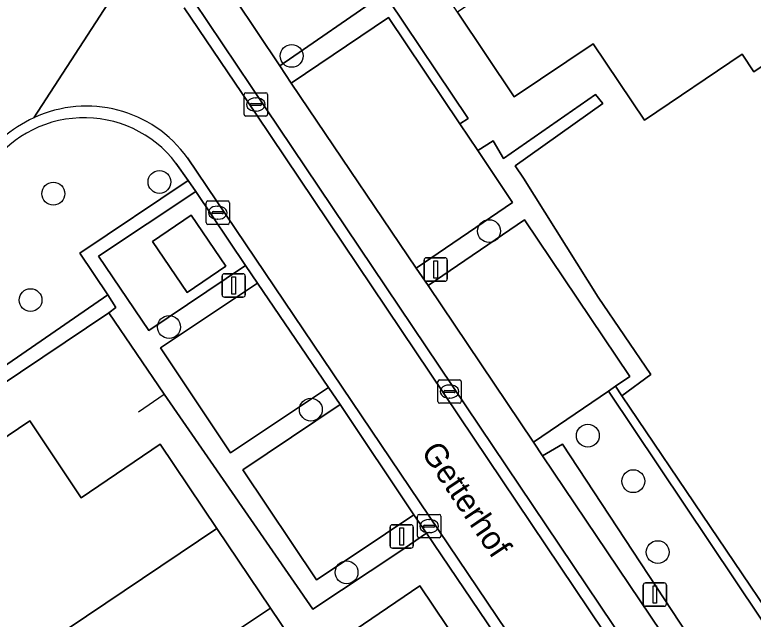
# Model space of a CAD drawing. Extents: x 158793 to 159888, y 384317 to 385256.
# Drawn here: x 158913.64 to 158945.21, y 384644.03 to 384669.88 of the extents above; entities that cross this region are included whole.
import ezdxf

# ---------------------------------------------------------------- set-up
doc = ezdxf.new("R2010")
doc.units = 0
for name, color, linetype in [('IMGEO_Berm_groen', 7, 'Continuous'), ('IMGEO_Boom', 7, 'Continuous'), ('IMGEO_Erf', 7, 'Continuous'), ('IMGEO_Groenvoorziening', 7, 'Continuous'), ('IMGEO_Haag', 7, 'Continuous'), ('IMGEO_Hek', 7, 'Continuous'), ('IMGEO_Kolk', 7, 'Continuous'), ('IMGEO_Lichtmast', 7, 'Continuous'), ('IMGEO_Openbare_ruimte_label', 7, 'Continuous'), ('IMGEO_Pand', 7, 'Continuous'), ('IMGEO_Parkeervlak_open', 7, 'Continuous'), ('IMGEO_Rijbaan_lokaal_open', 7, 'Continuous'), ('IMGEO_Voetpad_open', 7, 'Continuous')]:
    doc.layers.add(name, color=color, linetype=linetype)

msp = doc.modelspace()

# ---------------------------------------------------------------- linework, layer by layer
at = {"layer": 'IMGEO_Berm_groen'}
for points in [[(158917.62, 384657.908), (158916.41, 384659.683), (158921.052, 384662.795), (158920.527, 384663.541)], [(158914.37, 384620.747), (158915.141, 384621.25), (158911.908, 384626.271), (158911.057, 384625.702), (158910.473, 384626.512), (158909.391, 384625.832), (158899.194, 384641.02), (158904.609, 384644.899), (158902.885, 384647.758), (158917.62, 384657.908)]]:
    msp.add_lwpolyline(points, dxfattribs=at)
msp.add_arc((158916.599, 384660.523), 4.953, 37.5405, 147.1324, dxfattribs=at)
at = {"layer": 'IMGEO_Boom'}
for centre in [(158925.473, 384668.121), (158919.821, 384662.733), (158915.283, 384662.229), (158933.915, 384660.629), (158914.31, 384657.679), (158920.233, 384656.527), (158926.294, 384652.998), (158938.137, 384651.883), (158940.079, 384649.936), (158941.126, 384646.903), (158927.821, 384646.037)]:
    msp.add_circle(centre, 0.489, dxfattribs=at)
at = {"layer": 'IMGEO_Erf'}
for points in [[(158970.042, 384650.292), (158941.462, 384692.581), (158927.478, 384683.208), (158931.293, 384677.308), (158928.892, 384675.59), (158929.234, 384675.051), (158928.67, 384674.688), (158930.599, 384671.589), (158929.431, 384670.782), (158929.615, 384670.527), (158933.026, 384665.451), (158932.663, 384665.215), (158933.428, 384664.074), (158934.085, 384664.494), (158934.527, 384663.737), (158938.467, 384666.472), (158938.773, 384666.087), (158935.034, 384663.418), (158935.39, 384662.897), (158938.577, 384657.798), (158940.832, 384654.504), (158939.596, 384653.583), (158950.919, 384636.829)], [(158904.737, 384643.112), (158907.129, 384644.742), (158905.762, 384646.758), (158914.28, 384652.511), (158916.47, 384649.231), (158919.852, 384651.521), (158922.28, 384647.917), (158924.575, 384644.51), (158926.138, 384642.19), (158930.948, 384645.466), (158934.462, 384640.251)]]:
    msp.add_lwpolyline(points, dxfattribs=at)
for points in [[(158947.724, 384673.172), (158949.095, 384671.141), (158948.169, 384670.516), (158948.678, 384669.761), (158945.239, 384667.438), (158944.73, 384668.193), (158940.56, 384665.377), (158938.371, 384668.635), (158934.992, 384666.367), (158932.559, 384669.992), (158930.189, 384673.523), (158933.543, 384675.788), (158931.351, 384679.049), (158936.953, 384682.824), (158934.795, 384686.024), (158938.817, 384688.731), (158942.46, 384683.305), (158940.633, 384682.078), (158943.587, 384677.678), (158946.74, 384679.793), (158950.125, 384674.776)], [(158935.269, 384640.755), (158935.742, 384641.055), (158931.239, 384647.707), (158930.053, 384646.895), (158926.376, 384644.46), (158920.02, 384653.654), (158917.65, 384657.141), (158903.486, 384647.632), (158905.26, 384644.832), (158899.805, 384640.906), (158909.685, 384626.219), (158910.802, 384626.858), (158911.256, 384626.177), (158922.042, 384633.454), (158922.226, 384633.163), (158925.099, 384628.623), (158936.517, 384636.347), (158935.783, 384637.416), (158937.012, 384638.256)]]:
    msp.add_lwpolyline(points, close=True, dxfattribs=at)
at = {"layer": 'IMGEO_Groenvoorziening'}
msp.add_lwpolyline([(158922.109, 384671.989), (158924.962, 384667.694), (158929.431, 384670.782), (158930.599, 384671.589), (158928.67, 384674.688), (158928.077, 384675.641), (158930.702, 384677.442), (158927, 384683.401), (158941.507, 384693.215), (158970.058, 384651.22), (158977.555, 384656.193), (158975.853, 384658.793), (158971.165, 384655.643), (158941.388, 384699.818)], dxfattribs=at)
for points in [[(158929.608, 384669.767), (158932.663, 384665.215), (158933.026, 384665.451), (158929.615, 384670.527), (158929.431, 384670.782), (158924.962, 384667.694), (158925.456, 384666.95)], [(158938.577, 384657.798), (158935.39, 384662.897), (158935.034, 384663.418), (158938.773, 384666.087), (158938.467, 384666.472), (158934.527, 384663.737), (158934.085, 384664.494), (158933.428, 384664.074), (158934.92, 384661.851), (158930.791, 384659.038), (158931.31, 384658.301), (158935.423, 384661.113), (158939.935, 384654.417), (158939.313, 384653.993), (158939.596, 384653.583), (158940.832, 384654.504)], [(158919.866, 384655.634), (158924.01, 384658.409), (158923.499, 384659.163), (158919.366, 384656.377), (158917.218, 384659.56), (158921.38, 384662.329), (158921.052, 384662.795), (158916.41, 384659.683), (158917.62, 384657.908), (158917.963, 384657.364), (158917.65, 384657.141), (158920.02, 384653.654), (158926.376, 384644.46), (158930.053, 384646.895), (158931.239, 384647.707), (158930.702, 384648.501), (158928.269, 384646.876), (158926.536, 384645.718), (158923.383, 384650.415), (158927.544, 384653.21), (158927.045, 384653.945), (158922.866, 384651.155)], [(158917.65, 384657.141), (158917.963, 384657.364), (158917.62, 384657.908), (158902.885, 384647.758), (158904.609, 384644.899), (158899.194, 384641.02), (158909.391, 384625.832), (158910.473, 384626.512), (158911.057, 384625.702), (158911.908, 384626.271), (158922.226, 384633.163), (158922.042, 384633.454), (158911.256, 384626.177), (158910.802, 384626.858), (158909.685, 384626.219), (158899.805, 384640.906), (158905.26, 384644.832), (158903.486, 384647.632)], [(158939.596, 384653.583), (158939.313, 384653.993), (158939.017, 384653.792), (158950.928, 384636.006), (158951.302, 384636.262), (158950.919, 384636.829)], [(158939.017, 384653.792), (158935.807, 384651.605), (158936.203, 384651.016), (158937.049, 384651.521), (158951.101, 384630.138), (158952.761, 384631.247), (158949.979, 384635.355), (158950.928, 384636.006)], [(158936.203, 384651.016), (158950.52, 384629.75), (158951.101, 384630.138), (158937.049, 384651.521)]]:
    msp.add_lwpolyline(points, close=True, dxfattribs=at)
at = {"layer": 'IMGEO_Haag'}
for points in [[(158929.615, 384670.527), (158929.431, 384670.782), (158924.962, 384667.694), (158925.456, 384666.95), (158929.608, 384669.767), (158932.663, 384665.215), (158933.026, 384665.451)], [(158938.577, 384657.798), (158935.39, 384662.897), (158935.034, 384663.418), (158938.773, 384666.087), (158938.467, 384666.472), (158934.527, 384663.737), (158934.085, 384664.494), (158933.428, 384664.074), (158934.92, 384661.851), (158930.791, 384659.038), (158931.31, 384658.301), (158935.423, 384661.113), (158939.935, 384654.417), (158939.313, 384653.993), (158939.596, 384653.583), (158940.832, 384654.504)], [(158939.596, 384653.583), (158939.313, 384653.993), (158939.017, 384653.792), (158950.928, 384636.006), (158951.302, 384636.262), (158950.919, 384636.829)], [(158936.203, 384651.016), (158950.52, 384629.75), (158951.101, 384630.138), (158937.049, 384651.521)]]:
    msp.add_lwpolyline(points, close=True, dxfattribs=at)
at = {"layer": 'IMGEO_Hek'}
msp.add_lwpolyline([(158918.924, 384652.902), (158920.02, 384653.654), (158917.65, 384657.141), (158903.486, 384647.632), (158905.26, 384644.832)], dxfattribs=at)
at = {"layer": 'IMGEO_Kolk'}
for p, q in [((158923.441, 384665.618), (158923.441, 384666.47)), ((158923.516, 384666.544), (158924.368, 384666.544)), ((158923.929, 384666.324), (158923.954, 384666.324)), ((158924.442, 384666.47), (158924.442, 384665.618)), ((158923.7, 384666.038), (158923.7, 384666.05)), ((158924.138, 384666.001), (158923.74, 384666.001)), ((158923.743, 384666.087), (158924.141, 384666.087)), ((158924.184, 384666.05), (158924.184, 384666.038)), ((158923.952, 384665.764), (158923.927, 384665.764)), ((158924.368, 384665.544), (158923.516, 384665.544)), ((158921.813, 384660.992), (158921.813, 384661.844)), ((158921.888, 384661.918), (158922.74, 384661.918)), ((158922.814, 384661.844), (158922.814, 384660.992)), ((158922.301, 384661.698), (158922.326, 384661.698)), ((158922.072, 384661.412), (158922.072, 384661.424)), ((158922.51, 384661.375), (158922.112, 384661.375)), ((158922.115, 384661.461), (158922.513, 384661.461)), ((158922.556, 384661.424), (158922.556, 384661.412)), ((158922.74, 384660.918), (158921.888, 384660.918)), ((158922.324, 384661.138), (158922.299, 384661.138)), ((158931.798, 384654.269), (158932.65, 384654.269)), ((158931.723, 384653.343), (158931.723, 384654.195)), ((158932.211, 384654.049), (158932.236, 384654.049)), ((158932.724, 384654.195), (158932.724, 384653.343)), ((158931.982, 384653.763), (158931.982, 384653.775)), ((158932.42, 384653.726), (158932.022, 384653.726)), ((158932.025, 384653.812), (158932.423, 384653.812)), ((158932.466, 384653.775), (158932.466, 384653.763)), ((158932.234, 384653.489), (158932.209, 384653.489)), ((158932.65, 384653.269), (158931.798, 384653.269)), ((158930.852, 384647.589), (158930.852, 384648.441)), ((158930.927, 384648.515), (158931.779, 384648.515)), ((158931.34, 384648.295), (158931.365, 384648.295)), ((158931.853, 384648.441), (158931.853, 384647.589)), ((158931.111, 384648.009), (158931.111, 384648.021)), ((158931.549, 384647.972), (158931.151, 384647.972)), ((158931.154, 384648.058), (158931.552, 384648.058)), ((158931.595, 384648.021), (158931.595, 384648.009)), ((158931.363, 384647.735), (158931.338, 384647.735)), ((158931.779, 384647.515), (158930.927, 384647.515))]:
    msp.add_line(p, q, dxfattribs=at)
for points in [[(158923.441, 384665.618), (158923.441, 384666.47)], [(158923.516, 384666.544), (158924.368, 384666.544)], [(158924.442, 384666.47), (158924.442, 384665.618)], [(158924.368, 384665.544), (158923.516, 384665.544)], [(158921.813, 384660.992), (158921.813, 384661.844)], [(158921.888, 384661.918), (158922.74, 384661.918)], [(158922.814, 384661.844), (158922.814, 384660.992)], [(158922.74, 384660.918), (158921.888, 384660.918)], [(158931.798, 384654.269), (158932.65, 384654.269)], [(158931.723, 384653.343), (158931.723, 384654.195)], [(158932.724, 384654.195), (158932.724, 384653.343)], [(158932.65, 384653.269), (158931.798, 384653.269)], [(158930.852, 384647.589), (158930.852, 384648.441)], [(158930.927, 384648.515), (158931.779, 384648.515)], [(158931.853, 384648.441), (158931.853, 384647.589)], [(158931.779, 384647.515), (158930.927, 384647.515)]]:
    msp.add_lwpolyline(points, dxfattribs=at)
for centre, radius, start, end in [((158923.518, 384666.468), 0.0765, 91.552, 178.448), ((158923.518, 384666.468), 0.0765, 91.552, 178.448), ((158924.366, 384666.468), 0.0765, 1.552, 88.448), ((158924.366, 384666.468), 0.0765, 1.552, 88.448), ((158923.74, 384666.047), 0.0403, 85.8775, 175.7526), ((158923.737, 384666.037), 0.0366, 178.938, 274.7102), ((158924.141, 384666.044), 0.043, 264.8664, 352.4533), ((158924.145, 384666.049), 0.0386, 1.7309, 96.639), ((158923.518, 384665.62), 0.0765, 181.552, 268.448), ((158923.518, 384665.62), 0.0765, 181.552, 268.448), ((158924.366, 384665.62), 0.0765, 271.552, 358.448), ((158924.366, 384665.62), 0.0765, 271.552, 358.448), ((158921.89, 384661.842), 0.0765, 91.552, 178.448), ((158921.89, 384661.842), 0.0765, 91.552, 178.448), ((158922.738, 384661.842), 0.0765, 1.552, 88.448), ((158922.738, 384661.842), 0.0765, 1.552, 88.448), ((158922.112, 384661.421), 0.0403, 85.8775, 175.7526), ((158922.109, 384661.411), 0.0366, 178.938, 274.7102), ((158922.513, 384661.418), 0.043, 264.8664, 352.4533), ((158922.517, 384661.423), 0.0386, 1.7309, 96.639), ((158921.89, 384660.994), 0.0765, 181.552, 268.448), ((158921.89, 384660.994), 0.0765, 181.552, 268.448), ((158922.738, 384660.994), 0.0765, 271.552, 358.448), ((158922.738, 384660.994), 0.0765, 271.552, 358.448), ((158931.8, 384654.193), 0.0765, 91.552, 178.448), ((158931.8, 384654.193), 0.0765, 91.552, 178.448), ((158932.648, 384654.193), 0.0765, 1.552, 88.448), ((158932.648, 384654.193), 0.0765, 1.552, 88.448), ((158932.022, 384653.772), 0.0403, 85.8775, 175.7526), ((158932.019, 384653.762), 0.0366, 178.938, 274.7102), ((158932.423, 384653.769), 0.043, 264.8664, 352.4533), ((158932.427, 384653.774), 0.0386, 1.7309, 96.639), ((158931.8, 384653.345), 0.0765, 181.552, 268.448), ((158931.8, 384653.345), 0.0765, 181.552, 268.448), ((158932.648, 384653.345), 0.0765, 271.552, 358.448), ((158932.648, 384653.345), 0.0765, 271.552, 358.448), ((158930.929, 384648.439), 0.0765, 91.552, 178.448), ((158930.929, 384648.439), 0.0765, 91.552, 178.448), ((158931.777, 384648.439), 0.0765, 1.552, 88.448), ((158931.777, 384648.439), 0.0765, 1.552, 88.448), ((158931.151, 384648.018), 0.0403, 85.8775, 175.7526), ((158931.148, 384648.008), 0.0366, 178.938, 274.7102), ((158931.552, 384648.015), 0.043, 264.8664, 352.4533), ((158931.556, 384648.02), 0.0386, 1.7309, 96.639), ((158930.929, 384647.591), 0.0765, 181.552, 268.448), ((158930.929, 384647.591), 0.0765, 181.552, 268.448), ((158931.777, 384647.591), 0.0765, 271.552, 358.448), ((158931.777, 384647.591), 0.0765, 271.552, 358.448)]:
    msp.add_arc(centre, radius, start, end, dxfattribs=at)
for centre, major_axis, ratio, start_param, end_param in [((158923.928, 384666.044), (-0.387, 0.002), 0.722429, 4.712389, 7.853982), ((158923.953, 384666.044), (-0.39, 0.002), 0.717154, 1.570796, 4.712389), ((158922.3, 384661.418), (-0.387, 0.002), 0.722429, 4.712389, 7.853982), ((158922.325, 384661.418), (-0.39, 0.002), 0.717154, 1.570796, 4.712389), ((158932.21, 384653.769), (-0.387, 0.002), 0.722429, 4.712389, 7.853982), ((158932.235, 384653.769), (-0.39, 0.002), 0.717154, 1.570796, 4.712389), ((158931.339, 384648.015), (-0.387, 0.002), 0.722429, 4.712389, 7.853982), ((158931.364, 384648.015), (-0.39, 0.002), 0.717154, 1.570796, 4.712389)]:
    msp.add_ellipse(centre, major_axis=major_axis, ratio=ratio, start_param=start_param, end_param=end_param, dxfattribs=at)
at = {"layer": 'IMGEO_Lichtmast'}
for p, q in [((158931.135, 384658.588), (158931.135, 384659.388)), ((158931.135, 384659.388), (158931.135, 384658.588)), ((158931.235, 384659.488), (158932.025, 384659.488)), ((158932.025, 384659.488), (158931.235, 384659.488)), ((158932.125, 384659.388), (158932.125, 384658.588)), ((158932.125, 384658.588), (158932.125, 384659.388)), ((158922.501, 384657.906), (158922.501, 384658.706)), ((158922.501, 384658.706), (158922.501, 384657.906)), ((158922.601, 384658.806), (158923.391, 384658.806)), ((158923.391, 384658.806), (158922.601, 384658.806)), ((158923.491, 384658.706), (158923.491, 384657.906)), ((158923.491, 384657.906), (158923.491, 384658.706)), ((158932.025, 384658.488), (158931.235, 384658.488)), ((158931.235, 384658.488), (158932.025, 384658.488)), ((158923.391, 384657.806), (158922.601, 384657.806)), ((158922.601, 384657.806), (158923.391, 384657.806)), ((158929.682, 384647.173), (158929.682, 384647.973)), ((158929.682, 384647.973), (158929.682, 384647.173)), ((158929.782, 384648.073), (158930.572, 384648.073)), ((158930.572, 384648.073), (158929.782, 384648.073)), ((158930.672, 384647.973), (158930.672, 384647.173)), ((158930.672, 384647.173), (158930.672, 384647.973)), ((158930.572, 384647.073), (158929.782, 384647.073)), ((158929.782, 384647.073), (158930.572, 384647.073)), ((158940.509, 384644.689), (158940.509, 384645.489)), ((158940.509, 384645.489), (158940.509, 384644.689)), ((158940.609, 384645.589), (158941.399, 384645.589)), ((158941.399, 384645.589), (158940.609, 384645.589)), ((158941.499, 384645.489), (158941.499, 384644.689)), ((158941.499, 384644.689), (158941.499, 384645.489)), ((158941.399, 384644.589), (158940.609, 384644.589)), ((158940.609, 384644.589), (158941.399, 384644.589))]:
    msp.add_line(p, q, dxfattribs=at)
for points in [[(158931.555, 384659.363), (158931.705, 384659.363), (158931.705, 384658.613), (158931.555, 384658.613), (158931.555, 384659.363)], [(158922.921, 384658.681), (158923.071, 384658.681), (158923.071, 384657.931), (158922.921, 384657.931), (158922.921, 384658.681)], [(158930.102, 384647.948), (158930.252, 384647.948), (158930.252, 384647.198), (158930.102, 384647.198), (158930.102, 384647.948)], [(158940.929, 384645.464), (158941.079, 384645.464), (158941.079, 384644.714), (158940.929, 384644.714), (158940.929, 384645.464)]]:
    msp.add_lwpolyline(points, dxfattribs=at)
for centre, start, end in [((158931.235, 384659.388), 90, 180), ((158931.235, 384659.388), 90, 180), ((158932.025, 384659.388), 0, 90), ((158932.025, 384659.388), 360, 90), ((158922.601, 384658.706), 90, 180), ((158922.601, 384658.706), 90, 180), ((158923.391, 384658.706), 0, 90), ((158923.391, 384658.706), 360, 90), ((158931.235, 384658.588), 180, 270), ((158931.235, 384658.588), 180, 270), ((158932.025, 384658.588), 270, 0), ((158932.025, 384658.588), 270, 0), ((158922.601, 384657.906), 180, 270), ((158922.601, 384657.906), 180, 270), ((158923.391, 384657.906), 270, 0), ((158923.391, 384657.906), 270, 0), ((158929.782, 384647.973), 90, 180), ((158929.782, 384647.973), 90, 180), ((158930.572, 384647.973), 0, 90), ((158930.572, 384647.973), 360, 90), ((158929.782, 384647.173), 180, 270), ((158929.782, 384647.173), 180, 270), ((158930.572, 384647.173), 270, 0), ((158930.572, 384647.173), 270, 0), ((158940.609, 384645.489), 90, 180), ((158940.609, 384645.489), 90, 180), ((158941.399, 384645.489), 0, 90), ((158941.399, 384645.489), 360, 90), ((158940.609, 384644.689), 180, 270), ((158940.609, 384644.689), 180, 270), ((158941.399, 384644.689), 270, 0), ((158941.399, 384644.689), 270, 0)]:
    msp.add_arc(centre, 0.1, start, end, dxfattribs=at)
at = {"layer": 'IMGEO_Pand'}
for points in [[(158947.724, 384673.172), (158950.125, 384674.776), (158946.74, 384679.793), (158943.587, 384677.678), (158943.725, 384677.475), (158932.559, 384669.992), (158934.992, 384666.367), (158938.371, 384668.635), (158940.56, 384665.377), (158944.73, 384668.193), (158945.239, 384667.438), (158948.678, 384669.761), (158948.169, 384670.516), (158949.095, 384671.141)], [(158921.004, 384658.011), (158922.656, 384659.135), (158921.175, 384661.311), (158919.523, 384660.186)], [(158922.28, 384647.917), (158919.852, 384651.521), (158916.47, 384649.231), (158914.28, 384652.511), (158905.762, 384646.758), (158907.129, 384644.742), (158904.737, 384643.112), (158907.976, 384638.304)], [(158918.797, 384640.665), (158924.575, 384644.51), (158922.28, 384647.917), (158907.976, 384638.304), (158911.211, 384633.503), (158913.616, 384635.123), (158915.091, 384632.933), (158915.823, 384633.472), (158916.324, 384632.791), (158919.879, 384635.339), (158919.342, 384636.067), (158920.865, 384637.19), (158921.037, 384637.317)], [(158930.948, 384645.466), (158926.138, 384642.19), (158924.575, 384644.51), (158918.797, 384640.665), (158921.037, 384637.317), (158920.865, 384637.19), (158922.204, 384635.199), (158925.241, 384637.242), (158925.827, 384636.371), (158926.167, 384636.6), (158927.06, 384635.272), (158934.462, 384640.251)]]:
    msp.add_lwpolyline(points, close=True, dxfattribs=at)
at = {"layer": 'IMGEO_Parkeervlak_open'}
for points in [[(158932.663, 384665.215), (158929.608, 384669.767), (158925.456, 384666.95), (158926.191, 384665.854), (158930.791, 384659.038), (158934.92, 384661.851), (158933.428, 384664.074)], [(158935.423, 384661.113), (158931.31, 384658.301), (158935.807, 384651.605), (158939.017, 384653.792), (158939.313, 384653.993), (158939.935, 384654.417)], [(158924.01, 384658.409), (158919.866, 384655.634), (158922.866, 384651.155), (158927.045, 384653.945)], [(158927.544, 384653.21), (158923.383, 384650.415), (158926.536, 384645.718), (158928.269, 384646.876), (158930.702, 384648.501)]]:
    msp.add_lwpolyline(points, close=True, dxfattribs=at)
at = {"layer": 'IMGEO_Rijbaan_lokaal_open'}
for points in [[(158919.564, 384673.366), (158914.448, 384665.471)], [(158914.448, 384665.471), (158919.564, 384673.366)], [(158920.881, 384670.173), (158923.955, 384665.633), (158949.957, 384626.932), (158968.418, 384639.524), (158968.134, 384639.947), (158950.085, 384627.638), (158924.353, 384665.905), (158921.285, 384670.455)], [(158941.972, 384632.67), (158949.064, 384622.099), (158970.35, 384636.65), (158968.418, 384639.524), (158949.957, 384626.932), (158923.955, 384665.633), (158920.881, 384670.173)], [(158920.527, 384663.541), (158921.052, 384662.795), (158921.38, 384662.329), (158923.499, 384659.163), (158924.01, 384658.409), (158927.045, 384653.945), (158927.544, 384653.21), (158930.702, 384648.501), (158931.239, 384647.707), (158935.742, 384641.055), (158937.439, 384638.548), (158937.764, 384638.068), (158939.325, 384635.681), (158916.548, 384620.432), (158916.491, 384620.393), (158916.788, 384619.978), (158916.847, 384620.015), (158940.033, 384635.577), (158921.019, 384663.762)], [(158921.019, 384663.762), (158940.033, 384635.577), (158916.847, 384620.015), (158916.788, 384619.978), (158918.623, 384617.027), (158918.871, 384617.212), (158941.972, 384632.67)]]:
    msp.add_lwpolyline(points, dxfattribs=at)
for centre, radius, start, end in [((158916.701, 384660.648), 5.324, 35.8028, 115.0399), ((158916.701, 384660.648), 5.324, 35.8028, 115.0399), ((158917.078, 384659.881), 6.178, 115.1979, 144.8814), ((158917.078, 384659.881), 6.178, 115.1979, 144.8814), ((158916.599, 384660.523), 4.953, 37.5405, 147.1324)]:
    msp.add_arc(centre, radius, start, end, dxfattribs=at)
at = {"layer": 'IMGEO_Voetpad_open'}
msp.add_lwpolyline([(158921.285, 384670.455), (158924.353, 384665.905), (158950.085, 384627.638), (158968.134, 384639.947), (158964.327, 384645.61), (158962.382, 384644.283), (158965.367, 384639.89), (158964.741, 384639.472), (158960.089, 384636.266), (158959.328, 384635.75), (158952.761, 384631.247), (158951.101, 384630.138), (158950.52, 384629.75), (158936.203, 384651.016), (158935.807, 384651.605), (158931.31, 384658.301), (158930.791, 384659.038), (158926.191, 384665.854), (158925.456, 384666.95), (158924.962, 384667.694), (158922.109, 384671.989)], dxfattribs=at)
for points in [[(158923.499, 384659.163), (158921.38, 384662.329), (158917.218, 384659.56), (158919.366, 384656.377)], [(158919.523, 384660.186), (158921.175, 384661.311), (158922.656, 384659.135), (158921.004, 384658.011)]]:
    msp.add_lwpolyline(points, close=True, dxfattribs=at)

# ---------------------------------------------------------------- texts
at = {"layer": 'IMGEO_Openbare_ruimte_label'}
msp.add_text('Getterhof', height=1, rotation=303.9445, dxfattribs=at).set_placement((158930.977, 384651.193))

doc.saveas('drawing.dxf')
